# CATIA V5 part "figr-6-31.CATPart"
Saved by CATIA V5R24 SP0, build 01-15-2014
Part number: Part1
Bounding box of the stored display mesh (mm): x -36 to 36, y -75 to 75, z -15.252 to 15.252
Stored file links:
  D:\KAVITA\CATIA V5-6R2014 Project_ Kavita\CATIA V5-6R2014_partfiles\Partfiles\c06_catia_v5-6r2014_prt\figr-6-31.CATPart
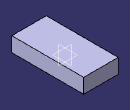
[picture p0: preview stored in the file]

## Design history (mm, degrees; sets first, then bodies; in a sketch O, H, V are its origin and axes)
Body1 (main body)
  Sketch1 on yz-plane, origin (0, 0, 0), H (0, 1, 0), V (0, 0, 1)
    line L1 (-75, 15.2515) -> (75, 15.2515)
    line L2 (75, 15.2515) -> (75, -15.2515)
    line L3 (75, -15.2515) -> (-75, -15.2515)
    line L4 (-75, -15.2515) -> (-75, 15.2515)
    axis line L5 (75, -15.2515) -> (-75, 15.2515)
    length L1 = 150
    horizontal: L1 H, L3 H
    vertical: L2 V, L4 V
    midpoint: O L5
  Pad1: profile Sketch1, direction (1, 0, 0), length 36, mirrored extent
